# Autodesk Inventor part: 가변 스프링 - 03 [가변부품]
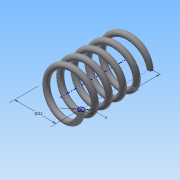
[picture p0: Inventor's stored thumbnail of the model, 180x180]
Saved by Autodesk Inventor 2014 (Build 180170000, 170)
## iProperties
Created: 2015-09
Part Number: 가변 스프링 - 03 [가변부품]
Material: 강철, 탄소
Document SubType Name: Modeling
Designer: study
Density: 1 g/cm^3
Appearance: 반연마
Author: study
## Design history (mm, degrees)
sketch "스케치1"
  geometry: L1 (0, 0)-(11, 0); L2 (11, 0)-(11, 36.561); L3 (11, 36.561)-(0, 36.561); L4 (0, 36.561)-(0, 0); C1 r 1.5 at (11, 0)
  constraints: 8 end point, 2 parallel, 1 centre point, 1 coincident, 1 horizontal, 1 perpendicular
  dimensions: "d0" = 22 diameter of L2 L4; "d1" = 36.5612 distance between parallel lines of L3 L1 (derived); "d2" = 3 diameter of C1
feature "코일1" sketch "스케치1" pitch "d3" = 10; turns "d5" = 5; dims "d4" = 36.5612 (= d1), "d6" = 0, angle "d7" = 90 deg, angle "d8" = 90 deg, "d9" = 0, "d10" = 0
node "작업 평면1"
sketch "스케치2"
  geometry: L1 (-12.5, 0)-(-9.5, 0) reference; L2 (-12.5, 0)-(-9.5, 0) reference; 1 further point
  constraints: 2 horizontal alignment
extrude "돌출1" cut sketch "스케치2" stored distance "d12" = 10; taper "d13" = 0 deg
node "작업 평면2"
sketch "스케치3"
  geometry: L1 (-9.5, 0)-(-12.5, 0) reference; 1 further point
  constraints: 1 horizontal alignment
extrude "돌출2" cut sketch "스케치3" stored distance "d15" = 10; taper "d16" = 0 deg
node "솔리드1"
node "절단 모서리 투영1"
node "절단 모서리 투영2"
node "절단 모서리 투영3"
other parameters: "d11" = 0, "d14" = 36.5612 (= d1)
